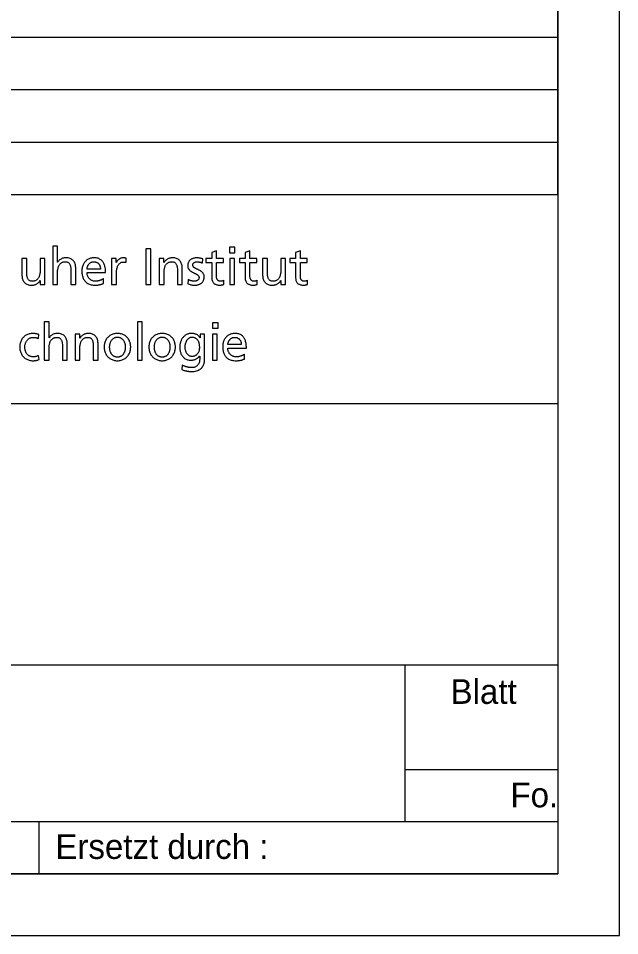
# Model space of a CAD drawing. Extents: x 0 to 168, y 0 to 119.
# Drawn here: x 158.47 to 168.2, y 0 to 14.85 of the extents above; entities that cross this region are included whole.
import ezdxf

# ---------------------------------------------------------------- set-up
doc = ezdxf.new("R2010")
doc.units = 0
doc.layers.add('90_Plankopf', color=7, linetype='Continuous')

msp = doc.modelspace()

# ---------------------------------------------------------------- linework, layer by layer
at = {"layer": '90_Plankopf'}
for p, q in [((167.2, 11.998), (167.2, 22.996)), ((131.624, 14.548), (167.2, 14.548)), ((131.624, 13.698), (167.2, 13.698)), ((131.624, 12.848), (167.2, 12.848)), ((131.624, 11.998), (167.2, 11.998)), ((131.624, 11.998), (167.2, 11.998)), ((167.2, 11.998), (167.2, 1)), ((167.2, 11.998), (167.2, 1)), ((160.211, 10.897), (160.211, 10.966)), ((161.446, 10.888), (161.453, 10.956)), ((159.794, 10.792), (159.577, 10.792)), ((159.577, 10.734), (159.877, 10.734)), ((159.845, 10.559), (159.845, 10.636)), ((161.214, 10.624), (161.21, 10.554)), ((161.792, 10.543), (161.792, 10.609)), ((162.333, 10.543), (162.333, 10.609)), ((163.149, 10.543), (163.149, 10.609)), ((158.79, 9.667), (158.797, 9.732)), ((162.075, 9.568), (161.857, 9.568)), ((161.857, 9.51), (162.157, 9.51)), ((158.8, 9.325), (158.794, 9.394)), ((162.125, 9.335), (162.125, 9.412)), ((161.119, 9.235), (161.111, 9.163)), ((150.4, 8.614), (167.2, 8.614)), ((150.4, 4.384), (167.2, 4.384)), ((164.729, 1.846), (164.729, 4.384)), ((164.729, 2.692), (167.2, 2.692)), ((150.4, 1.846), (167.2, 1.846)), ((158.8, 1), (158.8, 1.846)), ((167.2, 1), (131.624, 1)), ((133.96, 1), (167.2, 1)), ((133.96, 1), (167.2, 1))]:
    msp.add_line(p, q, dxfattribs=at)
for points in [[(0, 0), (168.2, 0), (168.2, 118.8), (0, 118.8)], [(5, 117.8), (167.2, 117.8), (167.2, 1), (5, 1)]]:
    msp.add_lwpolyline(points, close=True, dxfattribs=at)
for points in [[(159.102, 10.902), (159.1, 10.902), (159.1, 11.16), (159.023, 11.16), (159.023, 10.541), (159.1, 10.541), (159.1, 10.736)], [(161.971, 11.056), (161.971, 11.144), (161.883, 11.144), (161.883, 11.056), (161.971, 11.056)], [(160.529, 10.541), (160.612, 10.541), (160.612, 11.117), (160.529, 11.117), (160.529, 10.541)], [(161.674, 10.669), (161.674, 10.899), (161.786, 10.899), (161.786, 10.962), (161.674, 10.962), (161.674, 11.084), (161.597, 11.059), (161.597, 10.962), (161.502, 10.962), (161.502, 10.899), (161.597, 10.899), (161.597, 10.653)], [(162.215, 10.669), (162.215, 10.899), (162.327, 10.899), (162.327, 10.962), (162.215, 10.962), (162.215, 11.084), (162.138, 11.059), (162.138, 10.962), (162.043, 10.962), (162.043, 10.899), (162.138, 10.899), (162.138, 10.653)], [(163.031, 10.669), (163.031, 10.899), (163.142, 10.899), (163.142, 10.962), (163.031, 10.962), (163.031, 11.084), (162.953, 11.059), (162.953, 10.962), (162.858, 10.962), (162.858, 10.899), (162.953, 10.899), (162.953, 10.653)], [(158.601, 10.744), (158.601, 10.962), (158.523, 10.962), (158.523, 10.712)], [(158.819, 10.608), (158.82, 10.608), (158.82, 10.541), (158.895, 10.541), (158.895, 10.962), (158.818, 10.962), (158.818, 10.767)], [(160.05, 10.897), (160.049, 10.897), (160.049, 10.962), (159.976, 10.962), (159.976, 10.541), (160.054, 10.541), (160.054, 10.733)], [(160.823, 10.895), (160.822, 10.895), (160.822, 10.962), (160.746, 10.962), (160.746, 10.541), (160.824, 10.541), (160.824, 10.736)], [(161.888, 10.962), (161.888, 10.541), (161.966, 10.541), (161.966, 10.962), (161.888, 10.962)], [(162.497, 10.744), (162.497, 10.962), (162.419, 10.962), (162.419, 10.712)], [(162.715, 10.608), (162.716, 10.608), (162.716, 10.541), (162.791, 10.541), (162.791, 10.962), (162.714, 10.962), (162.714, 10.767)], [(159.317, 10.759), (159.317, 10.541), (159.395, 10.541), (159.395, 10.791)], [(161.041, 10.759), (161.041, 10.541), (161.119, 10.541), (161.119, 10.791)], [(158.964, 9.678), (158.962, 9.678), (158.962, 9.936), (158.884, 9.936), (158.884, 9.317), (158.962, 9.317), (158.962, 9.512)], [(160.393, 9.317), (160.47, 9.317), (160.47, 9.936), (160.393, 9.936), (160.393, 9.317)], [(161.699, 9.832), (161.699, 9.92), (161.611, 9.92), (161.611, 9.832), (161.699, 9.832)], [(159.461, 9.671), (159.459, 9.671), (159.459, 9.738), (159.384, 9.738), (159.384, 9.317), (159.461, 9.317), (159.461, 9.512)], [(161.479, 9.335), (161.479, 9.738), (161.407, 9.738), (161.407, 9.676), (161.406, 9.676)], [(161.606, 9.738), (161.606, 9.317), (161.684, 9.317), (161.684, 9.738), (161.606, 9.738)], [(159.179, 9.535), (159.179, 9.317), (159.257, 9.317), (159.257, 9.567)], [(159.679, 9.535), (159.679, 9.317), (159.756, 9.317), (159.756, 9.567)], [(161.4, 9.382), (161.401, 9.382), (161.401, 9.341)]]:
    msp.add_lwpolyline(points, dxfattribs=at)
for points in [[(159.1, 10.736), (159.1, 10.762), (159.103, 10.785), (159.108, 10.806), (159.113, 10.827), (159.121, 10.846), (159.131, 10.861), (159.142, 10.876), (159.155, 10.888), (159.171, 10.897), (159.187, 10.905), (159.206, 10.909), (159.228, 10.909), (159.251, 10.908), (159.268, 10.902), (159.281, 10.89), (159.295, 10.879), (159.304, 10.862), (159.309, 10.841), (159.315, 10.819), (159.317, 10.792), (159.317, 10.759)], [(159.395, 10.791), (159.395, 10.829), (159.389, 10.861), (159.378, 10.888), (159.367, 10.915), (159.35, 10.936), (159.327, 10.95), (159.303, 10.965), (159.274, 10.972), (159.237, 10.972), (159.208, 10.972), (159.181, 10.966), (159.158, 10.954), (159.135, 10.942), (159.116, 10.924), (159.102, 10.902)], [(159.877, 10.734), (159.877, 10.768), (159.874, 10.8), (159.868, 10.829), (159.861, 10.857), (159.851, 10.882), (159.837, 10.904), (159.822, 10.925), (159.803, 10.942), (159.78, 10.954), (159.756, 10.966), (159.726, 10.972), (159.691, 10.972), (159.661, 10.972), (159.635, 10.967), (159.61, 10.956), (159.586, 10.946), (159.565, 10.931), (159.548, 10.912), (159.531, 10.893), (159.517, 10.871), (159.508, 10.845), (159.499, 10.819), (159.494, 10.79), (159.494, 10.759), (159.494, 10.725), (159.498, 10.694), (159.507, 10.666), (159.516, 10.638), (159.529, 10.614), (159.547, 10.594), (159.565, 10.574), (159.587, 10.558), (159.615, 10.548), (159.642, 10.537), (159.675, 10.531), (159.712, 10.531), (159.735, 10.531), (159.754, 10.533), (159.771, 10.536), (159.787, 10.539), (159.801, 10.543), (159.813, 10.547), (159.824, 10.551), (159.835, 10.555), (159.845, 10.559)], [(159.577, 10.792), (159.578, 10.806), (159.581, 10.82), (159.586, 10.833), (159.591, 10.847), (159.598, 10.86), (159.607, 10.871), (159.616, 10.883), (159.627, 10.892), (159.641, 10.899), (159.654, 10.906), (159.671, 10.909), (159.69, 10.909), (159.706, 10.909), (159.721, 10.906), (159.734, 10.9), (159.747, 10.894), (159.758, 10.886), (159.767, 10.875), (159.776, 10.864), (159.783, 10.852), (159.787, 10.838), (159.792, 10.823), (159.794, 10.808), (159.794, 10.792)], [(160.211, 10.966), (160.206, 10.967), (160.201, 10.968), (160.196, 10.969), (160.191, 10.97), (160.186, 10.971), (160.18, 10.971), (160.174, 10.972), (160.168, 10.972), (160.16, 10.972), (160.145, 10.972), (160.131, 10.969), (160.116, 10.962), (160.102, 10.956), (160.09, 10.947), (160.078, 10.936), (160.067, 10.925), (160.057, 10.912), (160.05, 10.897)], [(160.054, 10.733), (160.054, 10.768), (160.059, 10.799), (160.068, 10.824), (160.078, 10.85), (160.091, 10.87), (160.108, 10.883), (160.125, 10.897), (160.145, 10.904), (160.168, 10.904), (160.175, 10.904), (160.182, 10.904), (160.19, 10.903), (160.197, 10.902), (160.204, 10.9), (160.211, 10.897)], [(161.119, 10.791), (161.119, 10.829), (161.113, 10.861), (161.102, 10.888), (161.091, 10.915), (161.074, 10.936), (161.05, 10.95), (161.027, 10.965), (160.997, 10.972), (160.961, 10.972), (160.941, 10.972), (160.922, 10.969), (160.904, 10.963), (160.886, 10.957), (160.87, 10.948), (160.856, 10.936), (160.842, 10.925), (160.831, 10.911), (160.823, 10.895)], [(160.824, 10.736), (160.824, 10.762), (160.826, 10.785), (160.832, 10.806), (160.837, 10.827), (160.844, 10.846), (160.855, 10.861), (160.865, 10.876), (160.879, 10.888), (160.895, 10.897), (160.911, 10.905), (160.93, 10.909), (160.952, 10.909), (160.974, 10.908), (160.992, 10.902), (161.005, 10.89), (161.018, 10.879), (161.027, 10.862), (161.033, 10.841), (161.039, 10.819), (161.041, 10.792), (161.041, 10.759)], [(161.453, 10.956), (161.438, 10.96), (161.422, 10.964), (161.407, 10.967), (161.391, 10.97), (161.374, 10.972), (161.356, 10.972), (161.336, 10.972), (161.316, 10.969), (161.298, 10.964), (161.28, 10.959), (161.264, 10.951), (161.251, 10.94), (161.237, 10.929), (161.227, 10.916), (161.219, 10.9), (161.212, 10.883), (161.208, 10.864), (161.208, 10.842), (161.208, 10.826), (161.211, 10.811), (161.218, 10.799), (161.225, 10.787), (161.233, 10.776), (161.244, 10.767), (161.255, 10.758), (161.267, 10.75), (161.28, 10.743), (161.293, 10.736), (161.306, 10.729), (161.319, 10.723), (161.331, 10.717), (161.343, 10.711), (161.354, 10.704), (161.365, 10.698), (161.374, 10.691), (161.38, 10.683), (161.387, 10.675), (161.39, 10.665), (161.39, 10.654), (161.39, 10.643), (161.388, 10.633), (161.383, 10.626), (161.378, 10.618), (161.372, 10.612), (161.364, 10.607), (161.356, 10.602), (161.348, 10.599), (161.338, 10.597), (161.329, 10.595), (161.32, 10.594), (161.311, 10.594), (161.303, 10.594), (161.294, 10.595), (161.283, 10.597), (161.272, 10.599), (161.26, 10.603), (161.248, 10.607), (161.236, 10.612), (161.225, 10.617), (161.214, 10.624)], [(161.21, 10.554), (161.228, 10.545), (161.247, 10.539), (161.267, 10.536), (161.286, 10.532), (161.306, 10.531), (161.326, 10.531), (161.345, 10.531), (161.363, 10.534), (161.38, 10.539), (161.398, 10.544), (161.414, 10.552), (161.428, 10.563), (161.441, 10.574), (161.452, 10.588), (161.46, 10.604), (161.469, 10.621), (161.473, 10.64), (161.473, 10.662), (161.473, 10.682), (161.469, 10.698), (161.463, 10.711), (161.456, 10.724), (161.447, 10.736), (161.437, 10.745), (161.426, 10.754), (161.414, 10.762), (161.401, 10.769), (161.388, 10.776), (161.375, 10.782), (161.362, 10.787), (161.349, 10.793), (161.337, 10.799), (161.327, 10.805), (161.316, 10.812), (161.307, 10.819), (161.3, 10.827), (161.294, 10.836), (161.291, 10.846), (161.29, 10.858), (161.291, 10.87), (161.294, 10.879), (161.301, 10.887), (161.308, 10.894), (161.317, 10.9), (161.328, 10.904), (161.339, 10.908), (161.351, 10.909), (161.365, 10.909), (161.369, 10.909), (161.375, 10.909), (161.383, 10.908), (161.39, 10.906), (161.398, 10.905), (161.406, 10.903), (161.414, 10.901), (161.422, 10.898), (161.429, 10.896), (161.436, 10.893), (161.442, 10.891), (161.446, 10.888)], [(158.523, 10.712), (158.523, 10.674), (158.529, 10.642), (158.54, 10.615), (158.551, 10.588), (158.568, 10.567), (158.592, 10.553), (158.615, 10.539), (158.645, 10.531), (158.681, 10.531), (158.701, 10.531), (158.72, 10.534), (158.738, 10.54), (158.756, 10.547), (158.772, 10.555), (158.786, 10.567), (158.8, 10.578), (158.811, 10.592), (158.819, 10.608)], [(158.818, 10.767), (158.818, 10.742), (158.815, 10.718), (158.81, 10.697), (158.805, 10.676), (158.798, 10.658), (158.787, 10.642), (158.777, 10.627), (158.763, 10.615), (158.747, 10.607), (158.731, 10.598), (158.712, 10.594), (158.69, 10.594), (158.668, 10.595), (158.65, 10.602), (158.637, 10.613), (158.624, 10.624), (158.614, 10.641), (158.609, 10.662), (158.603, 10.684), (158.601, 10.711), (158.601, 10.744)], [(159.845, 10.636), (159.84, 10.632), (159.833, 10.628), (159.824, 10.623), (159.815, 10.618), (159.804, 10.614), (159.792, 10.609), (159.78, 10.605), (159.768, 10.601), (159.754, 10.598), (159.741, 10.596), (159.728, 10.594), (159.715, 10.594), (159.697, 10.594), (159.679, 10.597), (159.663, 10.604), (159.646, 10.611), (159.631, 10.621), (159.618, 10.633), (159.605, 10.645), (159.595, 10.66), (159.588, 10.677), (159.581, 10.694), (159.577, 10.713), (159.577, 10.734)], [(162.419, 10.712), (162.419, 10.674), (162.425, 10.642), (162.436, 10.615), (162.447, 10.588), (162.464, 10.567), (162.487, 10.553), (162.511, 10.539), (162.54, 10.531), (162.577, 10.531), (162.596, 10.531), (162.615, 10.534), (162.633, 10.54), (162.651, 10.547), (162.667, 10.555), (162.682, 10.567), (162.696, 10.578), (162.707, 10.592), (162.715, 10.608)], [(162.714, 10.767), (162.714, 10.742), (162.711, 10.718), (162.706, 10.697), (162.701, 10.676), (162.693, 10.658), (162.683, 10.642), (162.672, 10.627), (162.659, 10.615), (162.643, 10.607), (162.627, 10.598), (162.608, 10.594), (162.586, 10.594), (162.563, 10.595), (162.546, 10.602), (162.533, 10.613), (162.519, 10.624), (162.51, 10.641), (162.505, 10.662), (162.499, 10.684), (162.497, 10.711), (162.497, 10.744)], [(161.597, 10.653), (161.597, 10.625), (161.602, 10.602), (161.613, 10.584), (161.623, 10.566), (161.638, 10.553), (161.657, 10.544), (161.677, 10.536), (161.699, 10.531), (161.726, 10.531), (161.739, 10.531), (161.751, 10.533), (161.762, 10.535), (161.773, 10.538), (161.784, 10.54), (161.792, 10.543)], [(161.792, 10.609), (161.787, 10.605), (161.779, 10.602), (161.771, 10.599), (161.762, 10.596), (161.751, 10.594), (161.74, 10.594), (161.728, 10.594), (161.717, 10.597), (161.707, 10.603), (161.697, 10.608), (161.689, 10.617), (161.683, 10.628), (161.677, 10.639), (161.674, 10.653), (161.674, 10.669)], [(162.138, 10.653), (162.138, 10.625), (162.143, 10.602), (162.153, 10.584), (162.164, 10.566), (162.179, 10.553), (162.198, 10.544), (162.217, 10.536), (162.24, 10.531), (162.267, 10.531), (162.28, 10.531), (162.292, 10.533), (162.303, 10.535), (162.314, 10.538), (162.324, 10.54), (162.333, 10.543)], [(162.333, 10.609), (162.327, 10.605), (162.32, 10.602), (162.311, 10.599), (162.303, 10.596), (162.292, 10.594), (162.28, 10.594), (162.268, 10.594), (162.257, 10.597), (162.248, 10.603), (162.238, 10.608), (162.23, 10.617), (162.224, 10.628), (162.218, 10.639), (162.215, 10.653), (162.215, 10.669)], [(162.953, 10.653), (162.953, 10.625), (162.959, 10.602), (162.969, 10.584), (162.979, 10.566), (162.994, 10.553), (163.014, 10.544), (163.033, 10.536), (163.056, 10.531), (163.083, 10.531), (163.095, 10.531), (163.107, 10.533), (163.118, 10.535), (163.13, 10.538), (163.14, 10.54), (163.149, 10.543)], [(163.149, 10.609), (163.143, 10.605), (163.136, 10.602), (163.127, 10.599), (163.118, 10.596), (163.108, 10.594), (163.096, 10.594), (163.084, 10.594), (163.073, 10.597), (163.063, 10.603), (163.053, 10.608), (163.046, 10.617), (163.04, 10.628), (163.034, 10.639), (163.031, 10.653), (163.031, 10.669)], [(158.797, 9.732), (158.789, 9.735), (158.78, 9.737), (158.77, 9.74), (158.759, 9.742), (158.748, 9.744), (158.736, 9.746), (158.724, 9.747), (158.713, 9.748), (158.703, 9.748), (158.67, 9.748), (158.641, 9.742), (158.615, 9.732), (158.589, 9.721), (158.566, 9.706), (158.547, 9.686), (158.528, 9.666), (158.514, 9.643), (158.504, 9.616), (158.493, 9.589), (158.488, 9.56), (158.488, 9.528), (158.488, 9.498), (158.494, 9.469), (158.504, 9.442), (158.514, 9.416), (158.529, 9.393), (158.548, 9.372), (158.567, 9.352), (158.589, 9.336), (158.616, 9.325), (158.642, 9.313), (158.671, 9.308), (158.703, 9.307), (158.712, 9.307), (158.722, 9.308), (158.733, 9.309), (158.744, 9.309), (158.755, 9.311), (158.767, 9.314), (158.778, 9.316), (158.789, 9.32), (158.8, 9.325)], [(158.794, 9.394), (158.786, 9.389), (158.777, 9.384), (158.768, 9.381), (158.759, 9.377), (158.749, 9.375), (158.739, 9.373), (158.729, 9.371), (158.72, 9.37), (158.711, 9.37), (158.691, 9.37), (158.673, 9.373), (158.658, 9.379), (158.643, 9.385), (158.63, 9.393), (158.618, 9.404), (158.607, 9.414), (158.598, 9.426), (158.591, 9.44), (158.584, 9.453), (158.579, 9.467), (158.576, 9.482), (158.572, 9.498), (158.571, 9.513), (158.571, 9.528), (158.571, 9.548), (158.574, 9.568), (158.58, 9.586), (158.586, 9.605), (158.594, 9.622), (158.606, 9.637), (158.617, 9.652), (158.631, 9.663), (158.648, 9.672), (158.665, 9.681), (158.684, 9.685), (158.706, 9.685), (158.719, 9.685), (158.732, 9.684), (158.746, 9.681), (158.761, 9.678), (158.775, 9.673), (158.79, 9.667)], [(158.962, 9.512), (158.962, 9.538), (158.965, 9.561), (158.97, 9.582), (158.975, 9.604), (158.982, 9.622), (158.993, 9.637), (159.003, 9.653), (159.017, 9.664), (159.033, 9.673), (159.049, 9.681), (159.068, 9.685), (159.09, 9.685), (159.112, 9.684), (159.13, 9.678), (159.143, 9.666), (159.156, 9.655), (159.165, 9.639), (159.171, 9.617), (159.177, 9.595), (159.179, 9.568), (159.179, 9.535)], [(159.257, 9.567), (159.257, 9.605), (159.251, 9.638), (159.24, 9.665), (159.229, 9.691), (159.212, 9.712), (159.188, 9.726), (159.165, 9.741), (159.135, 9.748), (159.099, 9.748), (159.069, 9.748), (159.043, 9.742), (159.02, 9.73), (158.997, 9.718), (158.978, 9.7), (158.964, 9.678)], [(159.756, 9.567), (159.756, 9.605), (159.751, 9.638), (159.739, 9.665), (159.728, 9.691), (159.711, 9.712), (159.688, 9.726), (159.665, 9.741), (159.635, 9.748), (159.598, 9.748), (159.579, 9.748), (159.56, 9.745), (159.542, 9.739), (159.524, 9.733), (159.508, 9.724), (159.494, 9.712), (159.48, 9.701), (159.468, 9.687), (159.461, 9.671)], [(159.461, 9.512), (159.461, 9.538), (159.464, 9.561), (159.469, 9.582), (159.474, 9.604), (159.482, 9.622), (159.492, 9.637), (159.503, 9.653), (159.516, 9.664), (159.532, 9.673), (159.548, 9.681), (159.567, 9.685), (159.589, 9.685), (159.612, 9.684), (159.63, 9.678), (159.643, 9.666), (159.656, 9.655), (159.665, 9.639), (159.67, 9.617), (159.676, 9.595), (159.679, 9.568), (159.679, 9.535)], [(160.279, 9.578), (160.276, 9.591), (160.273, 9.604), (160.268, 9.616), (160.258, 9.643), (160.244, 9.666), (160.225, 9.686), (160.206, 9.706), (160.183, 9.721), (160.157, 9.732), (160.131, 9.742), (160.102, 9.748), (160.07, 9.748), (160.038, 9.748), (160.008, 9.742), (159.982, 9.732), (159.956, 9.721), (159.933, 9.706), (159.914, 9.686), (159.895, 9.666), (159.881, 9.643), (159.871, 9.616), (159.86, 9.589), (159.855, 9.56), (159.855, 9.528)], [(159.938, 9.528), (159.938, 9.548), (159.941, 9.568), (159.947, 9.586), (159.953, 9.605), (159.961, 9.622), (159.973, 9.637), (159.984, 9.652), (159.998, 9.663), (160.014, 9.672), (160.03, 9.681), (160.049, 9.685), (160.07, 9.685), (160.09, 9.685), (160.109, 9.681), (160.125, 9.672), (160.141, 9.663), (160.155, 9.652), (160.166, 9.637), (160.178, 9.622), (160.186, 9.605), (160.192, 9.586), (160.198, 9.568), (160.201, 9.548), (160.201, 9.528), (160.201, 9.513), (160.199, 9.498), (160.196, 9.482), (160.193, 9.467), (160.188, 9.453), (160.181, 9.44), (160.174, 9.426), (160.166, 9.414), (160.155, 9.404), (160.145, 9.393), (160.133, 9.385), (160.118, 9.379), (160.104, 9.373), (160.088, 9.37), (160.07, 9.37), (160.052, 9.37), (160.035, 9.373), (160.021, 9.379), (160.007, 9.385), (159.994, 9.393), (159.984, 9.404), (159.973, 9.414), (159.965, 9.426), (159.958, 9.44), (159.951, 9.453), (159.946, 9.467), (159.943, 9.482), (159.939, 9.498), (159.938, 9.513), (159.938, 9.528)], [(161.003, 9.578), (161, 9.591), (160.997, 9.604), (160.992, 9.616), (160.982, 9.643), (160.968, 9.666), (160.949, 9.686), (160.93, 9.706), (160.907, 9.721), (160.881, 9.732), (160.855, 9.742), (160.826, 9.748), (160.794, 9.748), (160.762, 9.748), (160.732, 9.742), (160.706, 9.732), (160.68, 9.721), (160.657, 9.706), (160.638, 9.686), (160.619, 9.666), (160.605, 9.643), (160.595, 9.616), (160.585, 9.589), (160.579, 9.56), (160.579, 9.528)], [(160.662, 9.528), (160.662, 9.548), (160.665, 9.568), (160.671, 9.586), (160.677, 9.605), (160.685, 9.622), (160.697, 9.637), (160.708, 9.652), (160.722, 9.663), (160.738, 9.672), (160.754, 9.681), (160.773, 9.685), (160.794, 9.685), (160.815, 9.685), (160.833, 9.681), (160.849, 9.672), (160.865, 9.663), (160.879, 9.652), (160.89, 9.637), (160.902, 9.622), (160.91, 9.605), (160.916, 9.586), (160.922, 9.568), (160.925, 9.548), (160.925, 9.528), (160.925, 9.513), (160.923, 9.498), (160.92, 9.482), (160.917, 9.467), (160.912, 9.453), (160.905, 9.44), (160.898, 9.426), (160.89, 9.414), (160.879, 9.404), (160.869, 9.393), (160.857, 9.385), (160.842, 9.379), (160.828, 9.373), (160.812, 9.37), (160.794, 9.37), (160.776, 9.37), (160.759, 9.373), (160.745, 9.379), (160.731, 9.385), (160.718, 9.393), (160.708, 9.404), (160.697, 9.414), (160.689, 9.426), (160.682, 9.44), (160.675, 9.453), (160.67, 9.467), (160.667, 9.482), (160.663, 9.498), (160.662, 9.513), (160.662, 9.528)], [(161.406, 9.676), (161.398, 9.691), (161.388, 9.704), (161.376, 9.715), (161.364, 9.725), (161.349, 9.734), (161.331, 9.739), (161.313, 9.745), (161.291, 9.748), (161.267, 9.748), (161.241, 9.748), (161.219, 9.744), (161.199, 9.735), (161.178, 9.727), (161.161, 9.715), (161.146, 9.7), (161.131, 9.686), (161.118, 9.669), (161.108, 9.65), (161.098, 9.631), (161.091, 9.611), (161.086, 9.589), (161.081, 9.568), (161.079, 9.546), (161.079, 9.524), (161.079, 9.497), (161.082, 9.471), (161.09, 9.446), (161.097, 9.421), (161.109, 9.399), (161.124, 9.38), (161.138, 9.361), (161.157, 9.345), (161.18, 9.334), (161.202, 9.323), (161.229, 9.318), (161.259, 9.317), (161.277, 9.317), (161.294, 9.32), (161.312, 9.324), (161.329, 9.329), (161.345, 9.337), (161.36, 9.346), (161.376, 9.356), (161.389, 9.368), (161.4, 9.382)], [(161.278, 9.38), (161.26, 9.38), (161.244, 9.384), (161.23, 9.392), (161.215, 9.4), (161.203, 9.411), (161.193, 9.425), (161.182, 9.438), (161.175, 9.454), (161.169, 9.472), (161.164, 9.49), (161.161, 9.509), (161.161, 9.529), (161.161, 9.543), (161.163, 9.558), (161.166, 9.572), (161.169, 9.587), (161.174, 9.601), (161.18, 9.615), (161.186, 9.628), (161.194, 9.64), (161.203, 9.651), (161.213, 9.661), (161.224, 9.67), (161.236, 9.676), (161.249, 9.682), (161.263, 9.685), (161.278, 9.685), (161.299, 9.685), (161.317, 9.681), (161.333, 9.672), (161.348, 9.664), (161.361, 9.652), (161.371, 9.637), (161.381, 9.622), (161.389, 9.605), (161.394, 9.585), (161.399, 9.566), (161.401, 9.545), (161.401, 9.523), (161.401, 9.503), (161.398, 9.485), (161.393, 9.467), (161.387, 9.45), (161.378, 9.435), (161.367, 9.422), (161.356, 9.409), (161.343, 9.399), (161.328, 9.391), (161.313, 9.384), (161.297, 9.38), (161.278, 9.38)], [(162.157, 9.51), (162.157, 9.544), (162.154, 9.576), (162.148, 9.605), (162.142, 9.634), (162.131, 9.659), (162.117, 9.68), (162.102, 9.701), (162.083, 9.718), (162.06, 9.73), (162.036, 9.742), (162.006, 9.748), (161.971, 9.748), (161.942, 9.748), (161.915, 9.743), (161.89, 9.732), (161.866, 9.722), (161.845, 9.707), (161.828, 9.688), (161.811, 9.669), (161.797, 9.647), (161.788, 9.621), (161.779, 9.595), (161.774, 9.567), (161.774, 9.535), (161.774, 9.501), (161.778, 9.47), (161.787, 9.442), (161.796, 9.414), (161.809, 9.39), (161.827, 9.37), (161.845, 9.35), (161.868, 9.334), (161.895, 9.324), (161.922, 9.313), (161.955, 9.308), (161.992, 9.307), (162.015, 9.308), (162.034, 9.309), (162.051, 9.312), (162.067, 9.315), (162.081, 9.319), (162.093, 9.323), (162.104, 9.327), (162.115, 9.331), (162.125, 9.335)], [(161.857, 9.568), (161.858, 9.582), (161.861, 9.596), (161.866, 9.609), (161.871, 9.623), (161.878, 9.636), (161.887, 9.647), (161.896, 9.659), (161.907, 9.668), (161.921, 9.675), (161.934, 9.682), (161.951, 9.685), (161.97, 9.685), (161.986, 9.685), (162.001, 9.682), (162.014, 9.676), (162.027, 9.67), (162.038, 9.662), (162.047, 9.651), (162.056, 9.64), (162.063, 9.628), (162.068, 9.614), (162.072, 9.6), (162.075, 9.584), (162.075, 9.568)], [(159.855, 9.528), (159.855, 9.498), (159.861, 9.469), (159.871, 9.442), (159.881, 9.416), (159.896, 9.393), (159.915, 9.372), (159.934, 9.352), (159.956, 9.336), (159.983, 9.325), (160.009, 9.313), (160.038, 9.308), (160.07, 9.307), (160.101, 9.308), (160.131, 9.313), (160.156, 9.325), (160.183, 9.336), (160.205, 9.352), (160.224, 9.372), (160.243, 9.393), (160.258, 9.416), (160.268, 9.442), (160.278, 9.469), (160.283, 9.498), (160.284, 9.528), (160.284, 9.545), (160.282, 9.562), (160.279, 9.578)], [(160.579, 9.528), (160.579, 9.498), (160.585, 9.469), (160.595, 9.442), (160.605, 9.416), (160.62, 9.393), (160.639, 9.372), (160.658, 9.352), (160.681, 9.336), (160.707, 9.325), (160.733, 9.313), (160.762, 9.308), (160.794, 9.307), (160.826, 9.308), (160.855, 9.313), (160.881, 9.325), (160.907, 9.336), (160.929, 9.352), (160.948, 9.372), (160.967, 9.393), (160.982, 9.416), (160.992, 9.442), (161.002, 9.469), (161.007, 9.498), (161.008, 9.528), (161.008, 9.545), (161.006, 9.562), (161.003, 9.578)], [(162.125, 9.412), (162.12, 9.408), (162.113, 9.404), (162.104, 9.399), (162.095, 9.394), (162.084, 9.39), (162.072, 9.385), (162.06, 9.381), (162.048, 9.377), (162.034, 9.374), (162.021, 9.372), (162.008, 9.37), (161.995, 9.37), (161.977, 9.37), (161.959, 9.374), (161.943, 9.38), (161.926, 9.387), (161.911, 9.397), (161.898, 9.409), (161.886, 9.421), (161.875, 9.436), (161.868, 9.453), (161.861, 9.471), (161.857, 9.49), (161.857, 9.51)], [(161.111, 9.163), (161.133, 9.155), (161.153, 9.149), (161.17, 9.145), (161.187, 9.141), (161.203, 9.138), (161.218, 9.136), (161.233, 9.135), (161.247, 9.134), (161.262, 9.134), (161.312, 9.134), (161.353, 9.142), (161.385, 9.158), (161.417, 9.174), (161.441, 9.196), (161.456, 9.226), (161.472, 9.256), (161.479, 9.293), (161.479, 9.335)], [(161.401, 9.341), (161.401, 9.311), (161.396, 9.286), (161.386, 9.264), (161.375, 9.243), (161.361, 9.226), (161.341, 9.214), (161.322, 9.203), (161.298, 9.197), (161.271, 9.197), (161.257, 9.197), (161.244, 9.197), (161.232, 9.199), (161.219, 9.2), (161.208, 9.203), (161.196, 9.206), (161.184, 9.209), (161.172, 9.212), (161.16, 9.217), (161.147, 9.222), (161.134, 9.228), (161.119, 9.235)]]:
    msp.add_open_spline(points, degree=3, dxfattribs=at)

# ---------------------------------------------------------------- texts
for s, p in [('Blatt', (165.463, 3.752)), ('Fo.', (166.432, 2.078)), ('Ersetzt durch :', (159.065, 1.242))]:
    msp.add_text(s, height=0.4, dxfattribs=at).set_placement(p)

doc.saveas('drawing.dxf')
